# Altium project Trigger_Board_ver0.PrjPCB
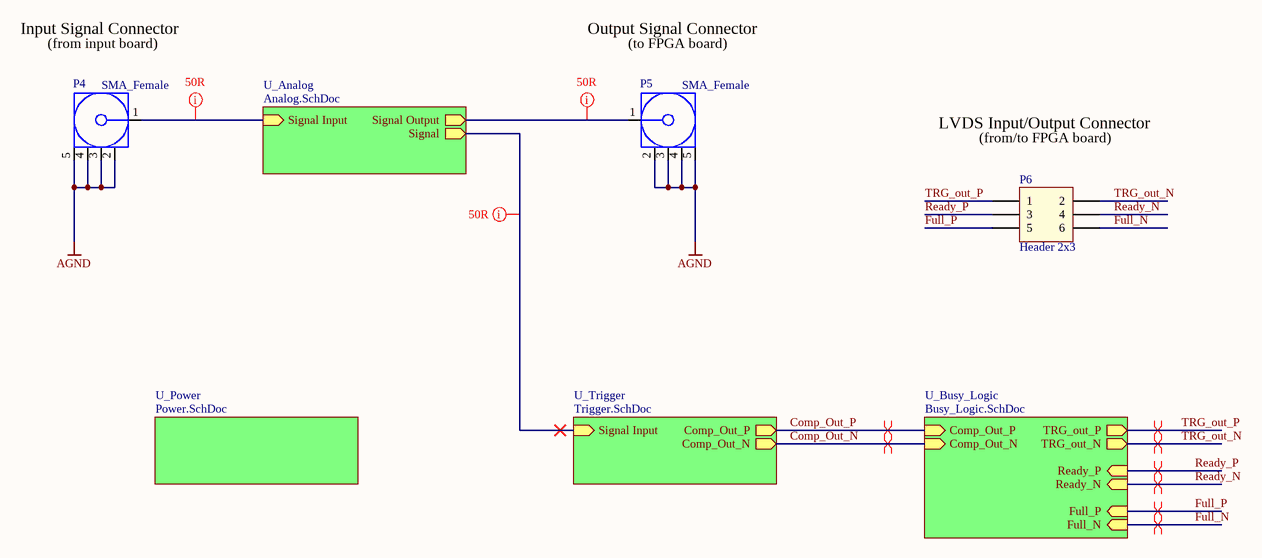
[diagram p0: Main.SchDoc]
5 sheets, 190 parts. Net scope: hierarchical (ports join the sheet entries above them; power ports are global).
Board file: Trigger_Board.PcbDoc
Sheets:
  Main.SchDoc
    U_Analog = Analog.SchDoc
    U_Power = Power.SchDoc
    U_Trigger = Trigger.SchDoc
    U_Busy_Logic = Busy_Logic.SchDoc

## Sheet Main.SchDoc
size A4

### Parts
P4  SMA_Female  [SMA5.08-H]
P5  SMA_Female  [SMA5.08-H]
P6  Header 2x3  [THT_HEADER_100MIL_2X3_MALE_SHROUDED]

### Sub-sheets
U_Analog = Analog.SchDoc: Signal Input (in), Signal Output (out), Signal (out)
U_Busy_Logic = Busy_Logic.SchDoc: TRG_out_P (out), TRG_out_N (out), Ready_P (in), Ready_N (in), Full_P (in), Full_N (in), Comp_Out_P (in), Comp_Out_N (in)
U_Power = Power.SchDoc: no entries
U_Trigger = Trigger.SchDoc: Signal Input (in), Comp_Out_P (out), Comp_Out_N (out)

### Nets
AGND: P4.2(GND) P4.3(GND) P4.4(GND) P4.5(GND) P5.2(GND) P5.3(GND) P5.4(GND) P5.5(GND)
Comp_Out_N: sheet U_Trigger/Comp_Out_N, sheet U_Busy_Logic/Comp_Out_N
Comp_Out_P: sheet U_Trigger/Comp_Out_P, sheet U_Busy_Logic/Comp_Out_P
Full_N: P6.6 ; sheet U_Busy_Logic/Full_N
Full_P: P6.5 ; sheet U_Busy_Logic/Full_P
Ready_N: P6.4 ; sheet U_Busy_Logic/Ready_N
Ready_P: P6.3 ; sheet U_Busy_Logic/Ready_P
TRG_out_N: P6.2 ; sheet U_Busy_Logic/TRG_out_N
TRG_out_P: P6.1 ; sheet U_Busy_Logic/TRG_out_P
NetJ1_1: sheet U_Analog/Signal, sheet U_Trigger/Signal Input
NetJ3_1: P4.1(Signal) ; sheet U_Analog/Signal Input
NetP5_1: P5.1(Signal) ; sheet U_Analog/Signal Output

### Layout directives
differential pair: Comp_Out_N, Comp_Out_P, Full_N, Full_P, Ready_N, Ready_P, TRG_out_N, TRG_out_P
net class 50R: NetJ1_1, NetJ3_1, NetP5_1

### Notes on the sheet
- Input Signal Connector
- (from input board)
- Output Signal Connector
- (to FPGA board)
- LVDS Input/Output Connector
- (from/to FPGA board)

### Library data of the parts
P6 = Header_2x3

## Sheet Analog.SchDoc
size A4
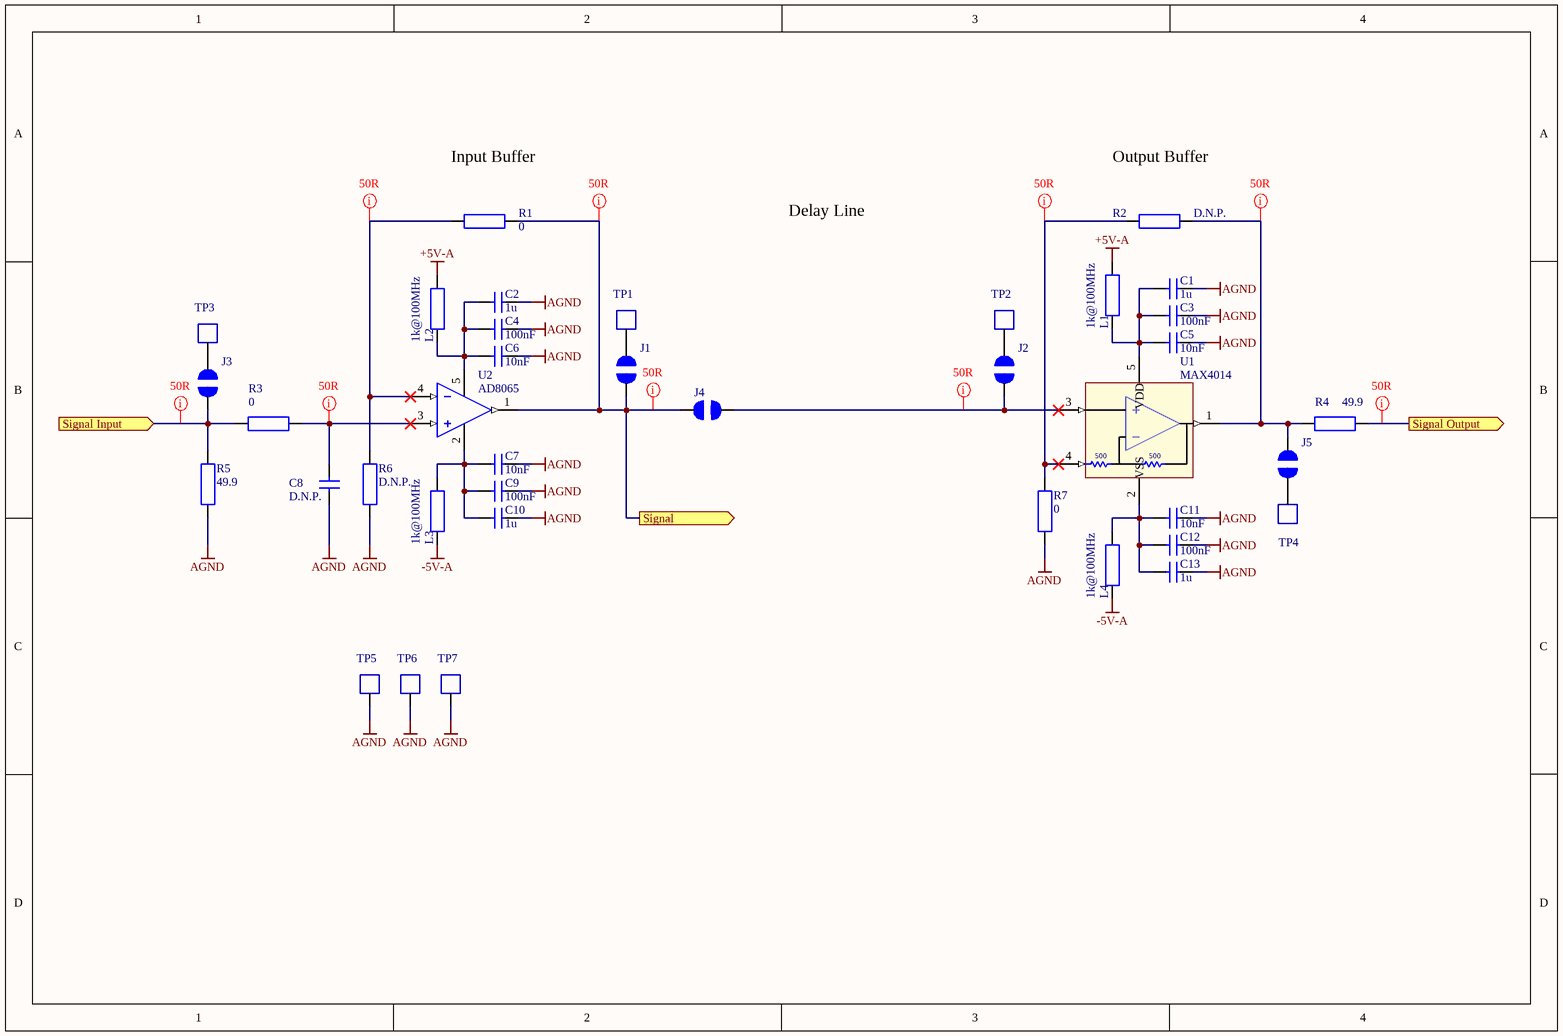
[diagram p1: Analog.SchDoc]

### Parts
C1  1u  [SMD_CAPACITOR_0603]
C2  1u  [SMD_CAPACITOR_0603]
C3  100nF  [SMD_CAPACITOR_0603]
C4  100nF  [SMD_CAPACITOR_0603]
C5  10nF  [SMD_CAPACITOR_0603]
C6  10nF  [SMD_CAPACITOR_0603]
C7  10nF  [SMD_CAPACITOR_0603]
C8  D.N.P.  [SMD_CAPACITOR_0603]
C9  100nF  [SMD_CAPACITOR_0603]
C10  1u  [SMD_CAPACITOR_0603]
C11  10nF  [SMD_CAPACITOR_0603]
C12  100nF  [SMD_CAPACITOR_0603]
C13  1u  [SMD_CAPACITOR_0603]
J1  SB  [SOLDER_BRIDGE_1MM]  (value not drawn)
J2  SB  [SOLDER_BRIDGE_1MM]  (value not drawn)
J3  SB  [SOLDER_BRIDGE_1MM]  (value not drawn)
J4  SB  [SOLDER_BRIDGE_2MM]  (value not drawn)
J5  SB  [SOLDER_BRIDGE_1MM]  (value not drawn)
L1  1k@100MHz  [SMD_RES_0603]
L2  1k@100MHz  [SMD_RES_0603]
L3  1k@100MHz  [SMD_RES_0603]
L4  1k@100MHz  [SMD_RES_0603]
R1  0  [SMD_RES_0603]
R2  D.N.P.  [SMD_RES_0603]
R3  0  [SMD_RES_0603]
R4  49.9  [SMD_RES_0603]
R5  49.9  [SMD_RES_0603]
R6  D.N.P.  [SMD_RES_0603]
R7  0  [SMD_RES_0603]
TP1  Test Pin  [PIn_1mm]  (value not drawn)
TP2  Test Pin  [PIn_1mm]  (value not drawn)
TP3  Test Pin  [PIn_1mm]  (value not drawn)
TP4  Test Pin  [PIn_1mm]  (value not drawn)
TP5  Test Pin  [PIn_1mm]  (value not drawn)
TP6  Test Pin  [PIn_1mm]  (value not drawn)
TP7  Test Pin  [PIn_1mm]  (value not drawn)
U1  MAX4014  [SMD_SOT-23-5]
U2  AD8065  [SMD_SOT-23-5]

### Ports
Signal (out), Signal Input (in), Signal Output (out)

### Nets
+5V-A: L1.2 L2.2
-5V-A: L3.1 L4.1
AGND: C1.2 C2.2 C3.2 C4.2 C5.2 C6.2 C7.2 C8.1 C9.2 C10.2 C11.2 C12.2 C13.2 R5.1 R6.1 R7.1 TP5.1 TP6.1 TP7.1
NetC1_1: C1.1 C3.1 C5.1 L1.1 U1.5(VDD)
NetC2_1: C2.1 C4.1 C6.1 L2.1 U2.5(VDD)
NetC7_1: C7.1 C9.1 C10.1 L3.2 U2.2(VSS)
NetC8_2: C8.2 R3.2 U2.3
NetC11_1: C11.1 C12.1 C13.1 L4.2 U1.2(VSS)
NetJ1_1: J1.1 J4.1 R1.2 U2.1 ; port Signal
NetJ1_2: J1.2 TP1.1
NetJ2_1: J2.1 J4.2 U1.3
NetJ2_2: J2.2 TP2.1
NetJ3_1: J3.1 R3.1 R5.2 ; port Signal Input
NetJ3_2: J3.2 TP3.1
NetJ5_1: J5.1 TP4.1
NetJ5_2: J5.2 R2.2 R4.1 U1.1
NetP5_1: R4.2 ; port Signal Output
NetR1_1: R1.1 R6.2 U2.4
NetR2_1: R2.1 R7.2 U1.4

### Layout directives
net class 50R: NetC8_2, NetJ1_1, NetJ2_1, NetJ3_1, NetJ5_2, NetP5_1, NetR1_1, NetR2_1

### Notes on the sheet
- Input Buffer
- Output Buffer
- Delay Line

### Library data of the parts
C1-C13 = Capacitor
J1-J3 J5 = Solder_Bridge_1mm
J4 = Solder_Bridge_2mm
L1-L4 = EMI_Ferrite_bead
R1-R7 = Resistor
TP1-TP7 = Test Pin: Connector

## Sheet Power.SchDoc
size A4
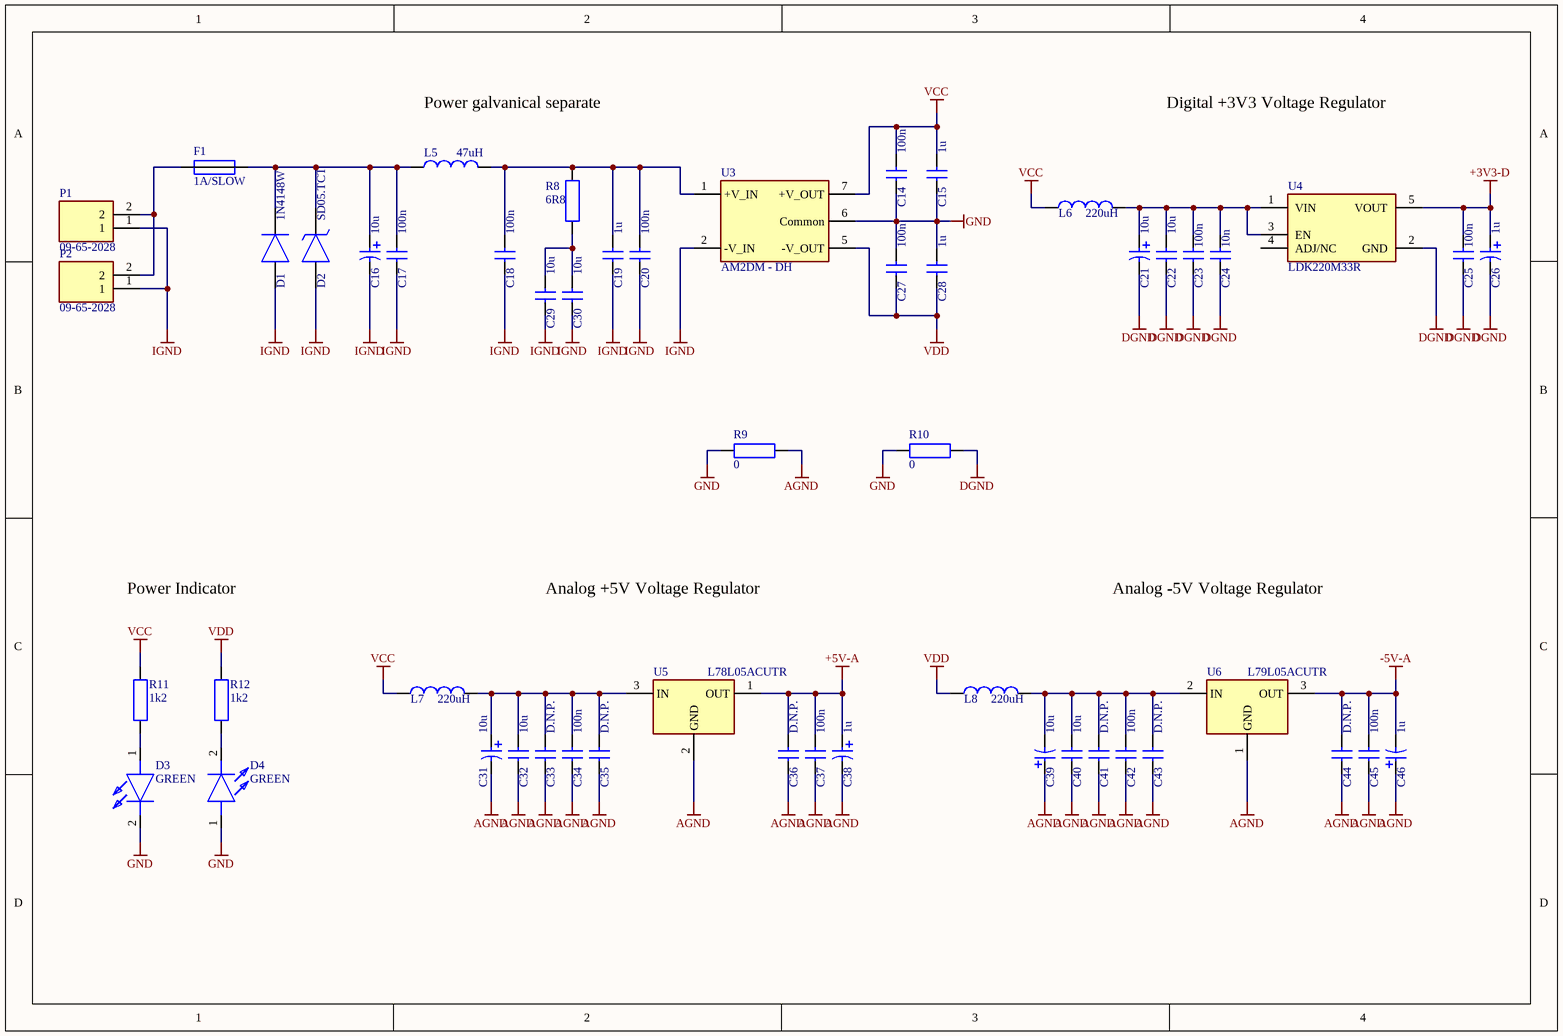
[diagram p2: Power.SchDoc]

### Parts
C14  100n  [SMD_CAPACITOR_0603]
C15  1u  [SMD_CAPACITOR_0603]
C16  10u  [SMD_CAP_POL_D5.0mm]
C17  100n  [SMD_CAPACITOR_0603]
C18  100n  [SMD_CAPACITOR_0603]
C19  1u  [SMD_CAPACITOR_0603]
C20  100n  [SMD_CAPACITOR_0603]
C21  10u  [SMD_CAP_POL_D5.0mm]
C22  10u  [SMD_CAPACITOR_1206]
C23  100n  [SMD_CAPACITOR_0603]
C24  10n  [SMD_CAPACITOR_0603]
C25  100n  [SMD_CAPACITOR_0603]
C26  1u  [SMD_CAPACITOR_POL_A_3216]
C27  100n  [SMD_CAPACITOR_0603]
C28  1u  [SMD_CAPACITOR_0603]
C29  10u  [SMD_CAPACITOR_1206]
C30  10u  [SMD_CAPACITOR_1206]
C31  10u  [SMD_CAP_POL_D5.0mm]
C32  10u  [SMD_CAPACITOR_1206]
C33  D.N.P.  [SMD_CAPACITOR_1206]
C34  100n  [SMD_CAPACITOR_0603]
C35  D.N.P.  [SMD_CAPACITOR_0603]
C36  D.N.P.  [SMD_CAPACITOR_0603]
C37  100n  [SMD_CAPACITOR_0603]
C38  1u  [SMD_CAPACITOR_POL_A_3216]
C39  10u  [SMD_CAP_POL_D5.0mm]
C40  10u  [SMD_CAPACITOR_1206]
C41  D.N.P.  [SMD_CAPACITOR_1206]
C42  100n  [SMD_CAPACITOR_0603]
C43  D.N.P.  [SMD_CAPACITOR_0603]
C44  D.N.P.  [SMD_CAPACITOR_0603]
C45  100n  [SMD_CAPACITOR_0603]
C46  1u  [SMD_CAPACITOR_POL_A_3216]
D1  1N4148W  [SMD_SOD-123]
D2  SD05.TCT  [SMD_SOD-323]
D3  GREEN  [SMD_LED_0603]
D4  GREEN  [SMD_LED_0603]
F1  1A/SLOW  [SMD_RESISTOR_1206]
L5  47uH  [SMD_INDUCTOR_7.3MM]
L6  220uH  [SMD_INDUCTOR_7.3MM]
L7  220uH  [SMD_INDUCTOR_7.3MM]
L8  220uH  [SMD_INDUCTOR_7.3MM]
P1  09-65-2028  [SHDR2W165P0X396_1X2_716X1062X1425P]
P2  09-65-2028  [SHDR2W165P0X396_1X2_716X1062X1425P]
R8  6R8  [SMD_RESISTOR_1206]
R9  0  [SMD_RESISTOR_0805]
R10  0  [SMD_RESISTOR_0805]
R11  1k2  [SMD_RES_0603]
R12  1k2  [SMD_RES_0603]
U3  AM2DM - DH  [AM2DM_dual_3]
U4  LDK220M33R  [SMD_SOT-23-5]
U5  L78L05ACUTR  [SOT-89_N]
U6  L79L05ACUTR  [SOT-89_N]

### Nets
+3V3-D: C25.2 C26.1 U4.5(VOUT)
+5V-A: C36.2 C37.2 C38.1 U5.1(OUT)
-5V-A: C44.2 C45.2 C46.2 U6.3(OUT)
AGND: C31.2 C32.1 C33.1 C34.1 C35.1 C36.1 C37.1 C38.2 C39.1 C40.1 C41.1 C42.1 C43.1 C44.1 C45.1 C46.1 R9.2 U5.2(GND) U6.1(GND)
DGND: C21.2 C22.1 C23.1 C24.1 C25.1 C26.2 R10.2 U4.2(GND)
GND: C14.1 C15.1 C27.2 C28.2 D3.2(K) D4.1(A) R9.1 R10.1 U3.6(Common)
IGND: C16.2 C17.1 C18.1 C19.1 C20.1 C29.1 C30.1 D1.1(A) D2.1(A) P1.1 P2.1 U3.2(-V_IN)
VCC: C14.2 C15.2 L6.1 L7.1 R11.1 U3.7(+V_OUT)
VDD: C27.1 C28.1 L8.1 R12.1 U3.5(-V_OUT)
NetC16_1: C16.1 C17.2 D1.2(K) D2.2(K) F1.2 L5.1
NetC18_2: C18.2 C19.2 C20.2 L5.2 R8.2 U3.1(+V_IN)
NetC21_1: C21.1 C22.2 C23.2 C24.2 L6.2 U4.1(VIN) U4.3(EN)
NetC29_2: C29.2 C30.2 R8.1
NetC31_1: C31.1 C32.2 C33.2 C34.2 C35.2 L7.2 U5.3(IN)
NetC39_2: C39.2 C40.2 C41.2 C42.2 C43.2 L8.2 U6.2(IN)
NetD3_1: D3.1(A) R11.2
NetD4_2: D4.2(K) R12.2
NetF1_1: F1.1 P1.2 P2.2

Not connected (* = marked no-connect by the designer): U4 4(ADJ/NC)

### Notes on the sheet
- Power galvanical separate
- Digital +3V3 Voltage Regulator
- Power Indicator
- Analog +5V Voltage Regulator
- Analog -5V Voltage Regulator

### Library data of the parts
C14 C15 C17-C20 C22-C25 C27-C30 C32-C37 C40-C45 = Capacitor
C16 C21 C26 C31 C38 C39 C46 = Capacitor_pol
D1 = Diode
D2 = TVS_Diode_unidirect
D3 D4 = LED
F1 = Fuse
L5-L8 = Inductor
P1 P2 = 09-65-2028: Connector; Manufacturer_Name: Molex; Allied_Number: 70374002
R8-R12 = Resistor
U4 = AP2204K-3.3TRG1

## Sheet Trigger.SchDoc
size A4
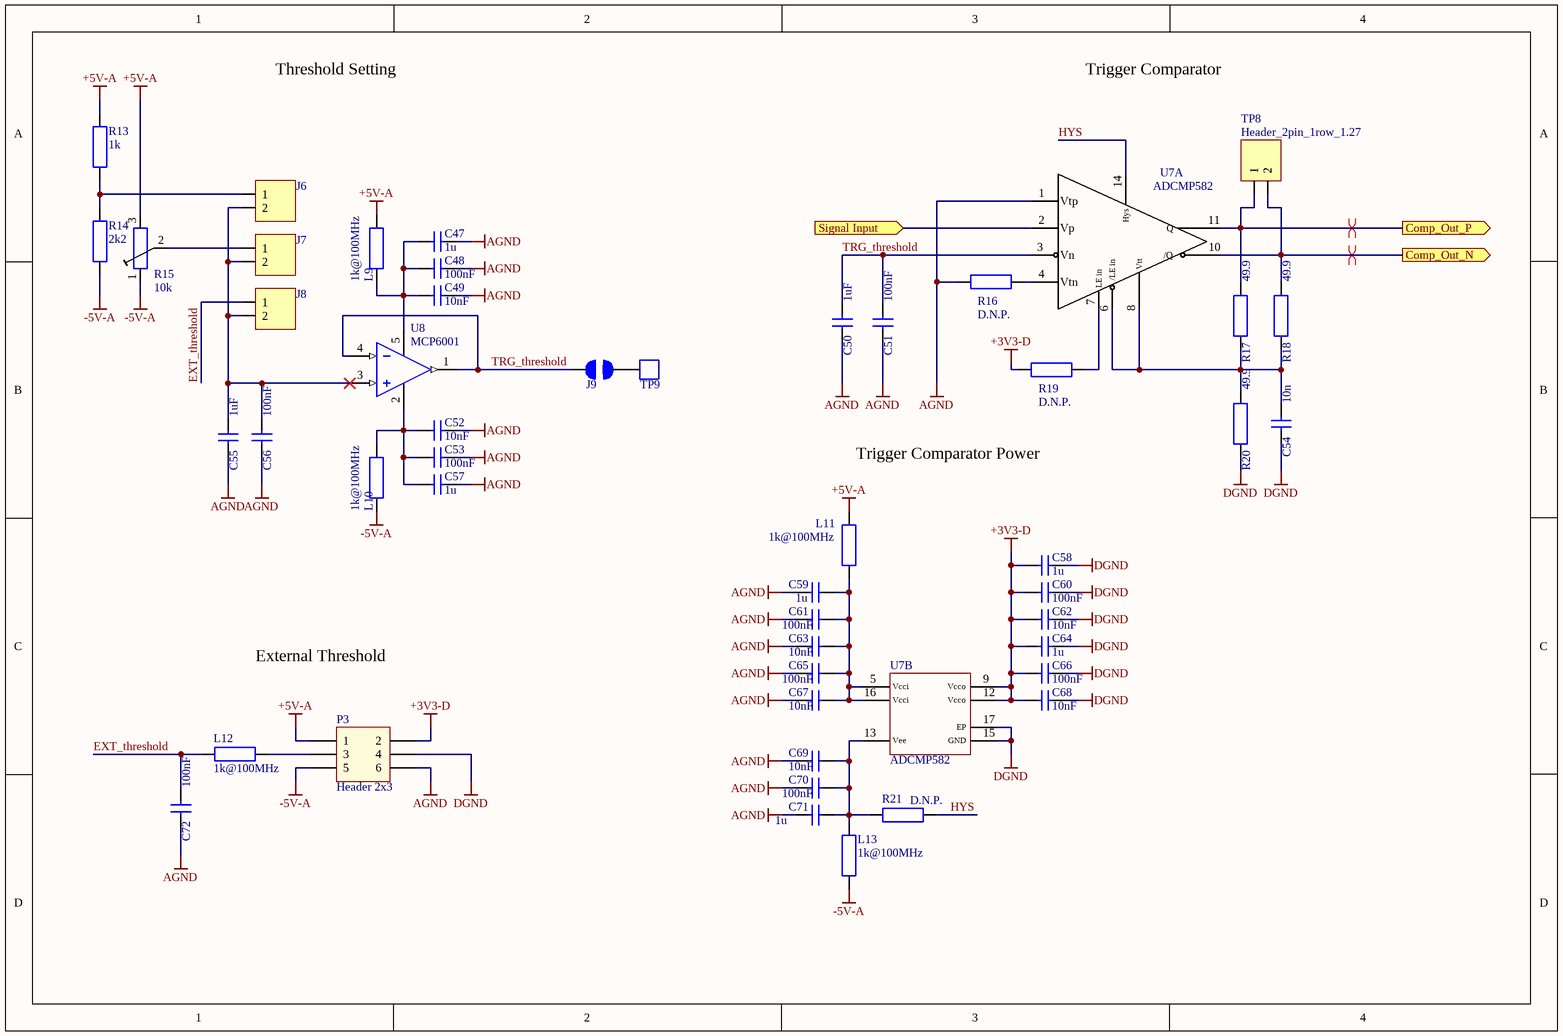
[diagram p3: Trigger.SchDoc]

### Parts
C47  1u  [SMD_CAPACITOR_0603]
C48  100nF  [SMD_CAPACITOR_0603]
C49  10nF  [SMD_CAPACITOR_0603]
C50  1uF  [SMD_CAPACITOR_0603]
C51  100nF  [SMD_CAPACITOR_0603]
C52  10nF  [SMD_CAPACITOR_0603]
C53  100nF  [SMD_CAPACITOR_0603]
C54  10n  [SMD_CAPACITOR_0603]
C55  1uF  [SMD_CAPACITOR_0603]
C56  100nF  [SMD_CAPACITOR_0603]
C57  1u  [SMD_CAPACITOR_0603]
C58  1u  [SMD_CAPACITOR_0603]
C59  1u  [SMD_CAPACITOR_0603]
C60  100nF  [SMD_CAPACITOR_0603]
C61  100nF  [SMD_CAPACITOR_0603]
C62  10nF  [SMD_CAPACITOR_0603]
C63  10nF  [SMD_CAPACITOR_0603]
C64  1u  [SMD_CAPACITOR_0603]
C65  100nF  [SMD_CAPACITOR_0603]
C66  100nF  [SMD_CAPACITOR_0603]
C67  10nF  [SMD_CAPACITOR_0603]
C68  10nF  [SMD_CAPACITOR_0603]
C69  10nF  [SMD_CAPACITOR_0603]
C70  100nF  [SMD_CAPACITOR_0603]
C71  1u  [SMD_CAPACITOR_0603]
C72  100nF  [SMD_CAPACITOR_0603]
J6  Header_2pin_1row  [61300211121]  (value not drawn)
J7  Header_2pin_1row  [61300211121]  (value not drawn)
J8  Header_2pin_1row  [61300211121]  (value not drawn)
J9  SB  [SOLDER_BRIDGE_1MM]  (value not drawn)
L9  1k@100MHz  [SMD_RES_0603]
L10  1k@100MHz  [SMD_RES_0603]
L11  1k@100MHz  [SMD_RES_0603]
L12  1k@100MHz  [SMD_RES_0603]
L13  1k@100MHz  [SMD_RES_0603]
P3  Header 2x3  [THT_HEADER_100MIL_2X3_MALE_SHROUDED]
R13  1k  [SMD_RES_0603]
R14  2k2  [SMD_RES_0603]
R15  10k  [THT_TRIM_3296Y1502LF]
R16  D.N.P.  [SMD_RES_0603]
R17  49.9  [SMD_RES_0603]
R18  49.9  [SMD_RES_0603]
R19  D.N.P.  [SMD_RES_0603]
R20  49.9  [SMD_RES_0603]
R21  D.N.P.  [SMD_RES_0603]
TP8  Header_2pin_1row_1.27  [HDRV2W40P0X127_1X2_254X210X420P]
TP9  Test Pin  [PIn_1mm]  (value not drawn)
U7  ADCMP582  [QFN50P300X300X80-17N-D]  (parts A,B of 2)
U8  MCP6001  [SMD_SOT-23-5]

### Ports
Comp_Out_N (out), Comp_Out_P (out), Signal Input (in)

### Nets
+3V3-D: C58.1 C60.1 C62.1 C64.1 C66.1 C68.1 P3.2 R19.1 U7.9(Vcco) U7.12(Vcco)
+5V-A: L9.2 L11.2 P3.1 R13.2 R15.3(CW)
-5V-A: L10.1 L13.1 P3.5 R14.1 R15.1(CCW)
AGND: C47.2 C48.2 C49.2 C50.1 C51.1 C52.2 C53.2 C55.1 C56.1 C57.2 C59.2 C61.2 C63.2 C65.2 C67.2 C69.2 C70.2 C71.2 C72.1 P3.6 R16.1 U7.1(Vtp)
DGND: C54.1 C58.2 C60.2 C62.2 C64.2 C66.2 C68.2 P3.4 R20.2 U7.15(GND) U7.17(EP)
Comp_Out_N: R18.1 TP8.2 U7.10(/Q) ; port Comp_Out_N
Comp_Out_P: R17.1 TP8.1 U7.11(Q) ; port Comp_Out_P
EXT_threshold: C72.2 J8.1 L12.2
HYS: R21.1 U7.14(Hys)
TRG_threshold: C50.2 C51.2 J9.2 U7.3(Vn) U8.1 U8.4
NetC47_1: C47.1 C48.1 C49.1 L9.1 U8.5(VDD)
NetC52_1: C52.1 C53.1 C57.1 L10.2 U8.2(VSS)
NetC54_2: C54.2 R17.2 R18.2 R20.1 U7.6(/LE_in) U7.8(Vtt)
NetC55_2: C55.2 C56.2 J6.2 J7.2 J8.2 U8.3
NetC59_1: C59.1 C61.1 C63.1 C65.1 C67.1 L11.1 U7.5(Vcci) U7.16(Vcci)
NetC69_1: C69.1 C70.1 C71.1 L13.2 R21.2 U7.13(Vee)
NetJ1_1: U7.2(Vp) ; port Signal Input
NetJ6_1: J6.1 R13.1 R14.2
NetJ7_1: J7.1 R15.2(WIPER)
NetJ9_1: J9.1 TP9.1
NetL12_1: L12.1 P3.3
NetR16_2: R16.2 U7.4(Vtn)
NetR19_2: R19.2 U7.7(LE_in)

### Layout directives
differential pair: Comp_Out_N, Comp_Out_P

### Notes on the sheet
- Threshold Setting
- Trigger Comparator
- Trigger Comparator Power
- External Threshold

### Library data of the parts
C47-C72 = Capacitor
J6-J8 = Header_2pin_1row: Manufacturer: Wurth Electronics
J9 = Solder_Bridge_1mm
L9-L13 = EMI_Ferrite_bead
P3 = Header_2x3
R13 R14 R16-R21 = Resistor
R15 = Resistor_trim
TP8 = Header_2pin_1row_1.27: Manufacturer: Harwin; Part Number: M50-3530242
TP9 = Test Pin: Connector
U7 = ADCMP582: Ultrafast Differential Comparator

## Sheet Busy_Logic.SchDoc
size A4
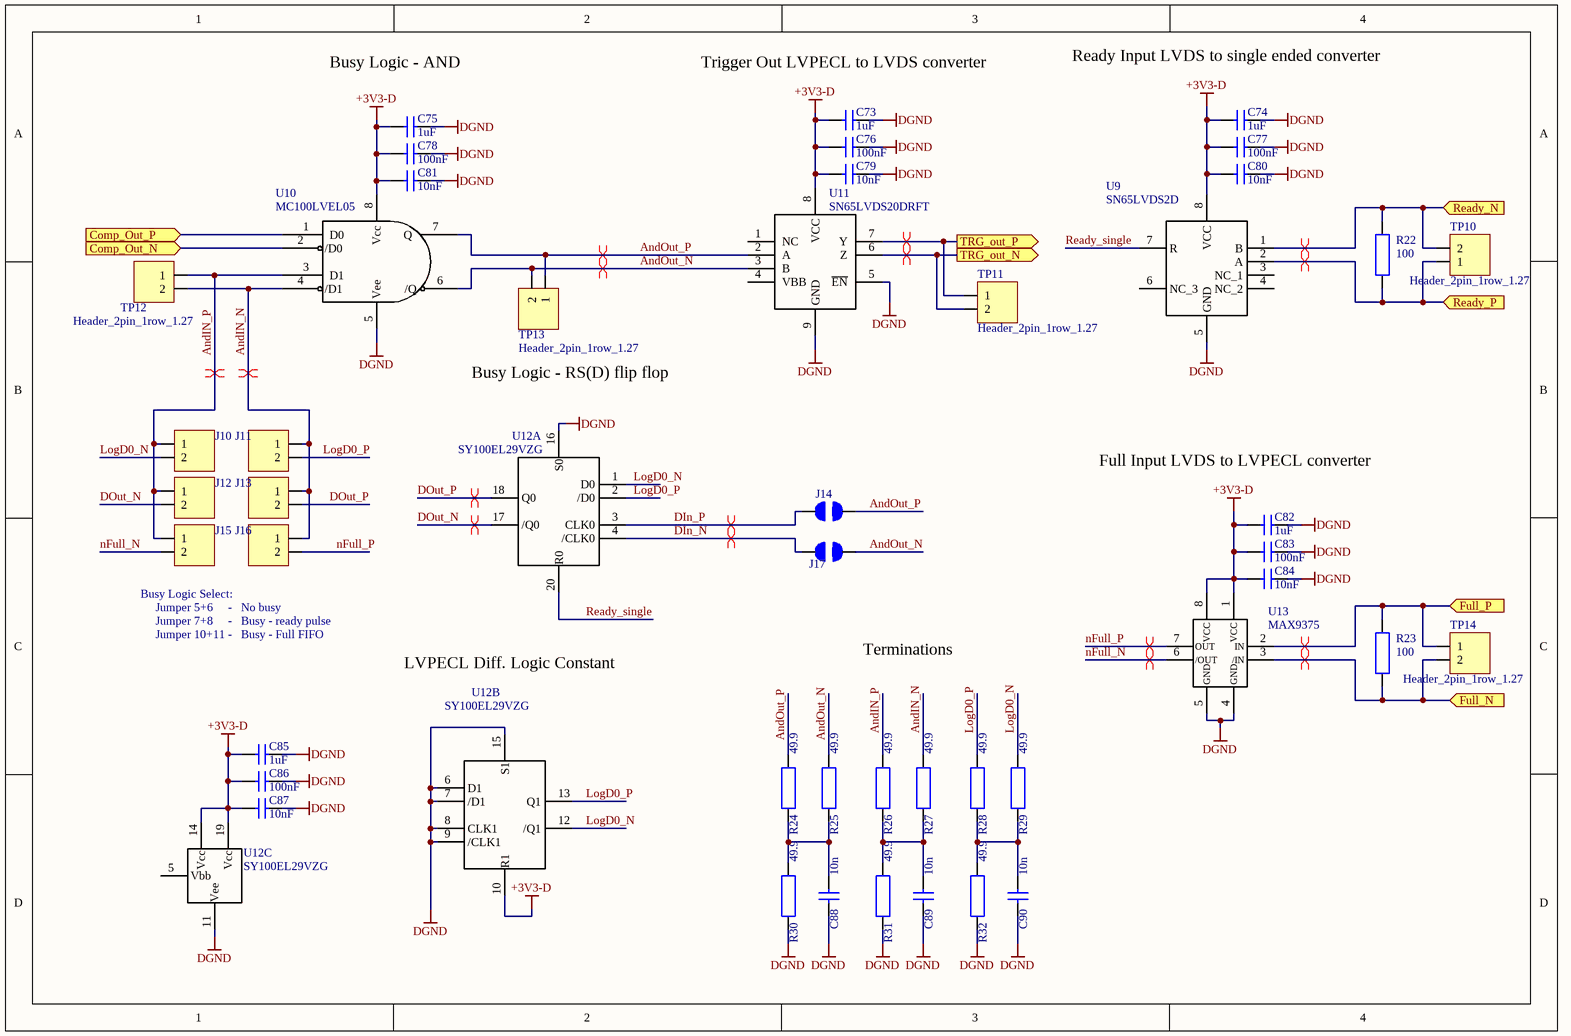
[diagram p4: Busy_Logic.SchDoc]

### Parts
C73  1uF  [SMD_CAPACITOR_0603]
C74  1uF  [SMD_CAPACITOR_0603]
C75  1uF  [SMD_CAPACITOR_0603]
C76  100nF  [SMD_CAPACITOR_0603]
C77  100nF  [SMD_CAPACITOR_0603]
C78  100nF  [SMD_CAPACITOR_0603]
C79  10nF  [SMD_CAPACITOR_0603]
C80  10nF  [SMD_CAPACITOR_0603]
C81  10nF  [SMD_CAPACITOR_0603]
C82  1uF  [SMD_CAPACITOR_0603]
C83  100nF  [SMD_CAPACITOR_0603]
C84  10nF  [SMD_CAPACITOR_0603]
C85  1uF  [SMD_CAPACITOR_0603]
C86  100nF  [SMD_CAPACITOR_0603]
C87  10nF  [SMD_CAPACITOR_0603]
C88  10n  [SMD_CAPACITOR_0603]
C89  10n  [SMD_CAPACITOR_0603]
C90  10n  [SMD_CAPACITOR_0603]
J10  Header_2pin_1row  [61300211121]  (value not drawn)
J11  Header_2pin_1row  [61300211121]  (value not drawn)
J12  Header_2pin_1row  [61300211121]  (value not drawn)
J13  Header_2pin_1row  [61300211121]  (value not drawn)
J14  SB  [SOLDER_BRIDGE_2MM]  (value not drawn)
J15  Header_2pin_1row  [61300211121]  (value not drawn)
J16  Header_2pin_1row  [61300211121]  (value not drawn)
J17  SB  [SOLDER_BRIDGE_2MM]  (value not drawn)
R22  100  [SMD_RES_0603]
R23  100  [SMD_RES_0603]
R24  49.9  [SMD_RES_0603]
R25  49.9  [SMD_RES_0603]
R26  49.9  [SMD_RES_0603]
R27  49.9  [SMD_RES_0603]
R28  49.9  [SMD_RES_0603]
R29  49.9  [SMD_RES_0603]
R30  49.9  [SMD_RES_0603]
R31  49.9  [SMD_RES_0603]
R32  49.9  [SMD_RES_0603]
TP10  Header_2pin_1row_1.27  [HDRV2W40P0X127_1X2_254X210X420P]
TP11  Header_2pin_1row_1.27  [HDRV2W40P0X127_1X2_254X210X420P]
TP12  Header_2pin_1row_1.27  [HDRV2W40P0X127_1X2_254X210X420P]
TP13  Header_2pin_1row_1.27  [HDRV2W40P0X127_1X2_254X210X420P]
TP14  Header_2pin_1row_1.27  [HDRV2W40P0X127_1X2_254X210X420P]
U9  SN65LVDS2D  [SMD_SOIC-8]
U10  MC100LVEL05  [SMD_SOIC-8]
U11  SN65LVDS20DRFT  [SON50P200X200X80-9N-D]
U12  SY100EL29VZG  [SOIC127P1030X265-20N]  (parts A,B,C of 3)
U13  MAX9375  [SOP65P490X110-8N]

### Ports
Comp_Out_N (in), Comp_Out_P (in), Full_N (in), Full_P (in), Ready_N (in), Ready_P (in), TRG_out_N (out), TRG_out_P (out)

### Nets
+3V3-D: C73.1 C74.1 C75.1 C76.1 C77.1 C78.1 C79.1 C80.1 C81.1 C82.1 C83.1 C84.1 C85.1 C86.1 C87.1 U9.8(VCC) U10.8(Vcc) U11.8(VCC) U12.10(R1) U12.14(Vcc) U12.19(Vcc) U13.1(VCC) U13.8(VCC)
DGND: C73.2 C74.2 C75.2 C76.2 C77.2 C78.2 C79.2 C80.2 C81.2 C82.2 C83.2 C84.2 C85.2 C86.2 C87.2 C88.1 C89.1 C90.1 R30.2 R31.2 R32.2 U9.5(GND) U10.5(Vee) U11.5(~{EN}) U11.9(GND) U12.6(D1) U12.7(/D1) U12.8(CLK1) U12.9(/CLK1) U12.11(Vee) U12.15(S1) U12.16(S0) U13.4(GND) U13.5(GND)
AndIN_N: J11.1 J13.1 J16.1 R27.1 TP12.2 U10.4(/D1)
AndIN_P: J10.1 J12.1 J15.1 R26.1 TP12.1 U10.3(D1)
AndOut_N: J17.2 R25.1 TP13.2 U10.6(/Q) U11.3(B)
AndOut_P: J14.2 R24.1 TP13.1 U10.7(Q) U11.2(A)
Comp_Out_N: U10.2(/D0) ; port Comp_Out_N
Comp_Out_P: U10.1(D0) ; port Comp_Out_P
DIn_N: J17.1 U12.4(/CLK0)
DIn_P: J14.1 U12.3(CLK0)
DOut_N: J12.2 U12.17(/Q0)
DOut_P: J13.2 U12.18(Q0)
Full_N: R23.2 TP14.2 U13.3(/IN) ; port Full_N
Full_P: R23.1 TP14.1 U13.2(IN) ; port Full_P
LogD0_N: J10.2 R29.1 U12.1(D0) U12.12(/Q1)
LogD0_P: J11.2 R28.1 U12.2(/D0) U12.13(Q1)
nFull_N: J15.2 U13.6(/OUT)
nFull_P: J16.2 U13.7(OUT)
Ready_N: R22.1 TP10.2 U9.1(B) ; port Ready_N
Ready_P: R22.2 TP10.1 U9.2(A) ; port Ready_P
Ready_single: U9.7(R) U12.20(R0)
TRG_out_N: TP11.2 U11.6(Z) ; port TRG_out_N
TRG_out_P: TP11.1 U11.7(Y) ; port TRG_out_P
NetC88_2: C88.2 R24.2 R25.2 R30.1
NetC89_2: C89.2 R26.2 R27.2 R31.1
NetC90_2: C90.2 R28.2 R29.2 R32.1

Not connected (* = marked no-connect by the designer): U9 3(NC_1) 4(NC_2) 6(NC_3); U11 1(NC) 4(VBB); U12 5(Vbb)

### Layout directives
differential pair: AndIN_N, AndIN_P, AndOut_N, AndOut_P, DIn_N, DIn_P, DOut_N, DOut_P, Full_N, Full_P, nFull_N, nFull_P, Ready_N, Ready_P, TRG_out_N, TRG_out_P

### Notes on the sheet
- Busy Logic - AND
- Trigger Out LVPECL to LVDS converter
- Ready Input LVDS to single ended converter
- Busy Logic - RS(D) flip flop
- Full Input LVDS to LVPECL converter
- Busy Logic Select:
  Jumper 5+6     -   No busy
  Jumper 7+8     -   Busy - ready pulse
  Jumper 10+11 -   Busy - Full FIFO
- Terminations
- LVPECL Diff. Logic Constant

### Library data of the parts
C73-C90 = Capacitor
J10-J13 J15 J16 = Header_2pin_1row: Manufacturer: Wurth Electronics
J14 J17 = Solder_Bridge_2mm
R22-R32 = Resistor
TP10-TP14 = Header_2pin_1row_1.27: as TP8 on sheet Trigger
U9 = SN65LVDS2D: SINGLE LVDS RECEIVER
U10 = MC100LVEL05: 3.3 V ECL 2‐Input Differential AND/NAND
U11 = SN65LVDS20DRFT: LVPECL AND LVDS REPEATER/TRANSLATOR WITH ENABLE
U12 = SY100EL29VZG: Dual Differential Data and Clock D Flip-Flop withSet and Reset
U13 = MAX9375: Single LVDS/Anything-to-LVPECL Translator

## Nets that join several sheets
+3V3-D: Power (C25.2 C26.1 U4.5), Trigger (10 pins), Busy_Logic (23 pins)
+5V-A: Analog (L1.2 L2.2), Power (C36.2 C37.2 C38.1 U5.1), Trigger (5 pins)
-5V-A: Analog (L3.1 L4.1), Power (C44.2 C45.2 C46.2 U6.3), Trigger (5 pins)
AGND: Main (8 pins), Analog (19 pins), Power (19 pins), Trigger (22 pins)
DGND: Power (8 pins), Trigger (11 pins), Busy_Logic (34 pins)
Comp_Out_N: Trigger (R18.1 TP8.2 U7.10), Busy_Logic (U10.2)
Comp_Out_P: Trigger (R17.1 TP8.1 U7.11), Busy_Logic (U10.1)
Full_N: Main (P6.6), Busy_Logic (R23.2 TP14.2 U13.3)
Full_P: Main (P6.5), Busy_Logic (R23.1 TP14.1 U13.2)
NetJ1_1: Analog (J1.1 J4.1 R1.2 U2.1), Trigger (U7.2)
NetJ3_1: Main (P4.1), Analog (J3.1 R3.1 R5.2)
NetP5_1: Main (P5.1), Analog (R4.2)
Ready_N: Main (P6.4), Busy_Logic (R22.1 TP10.2 U9.1)
Ready_P: Main (P6.3), Busy_Logic (R22.2 TP10.1 U9.2)
TRG_out_N: Main (P6.2), Busy_Logic (TP11.2 U11.6)
TRG_out_P: Main (P6.1), Busy_Logic (TP11.1 U11.7)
